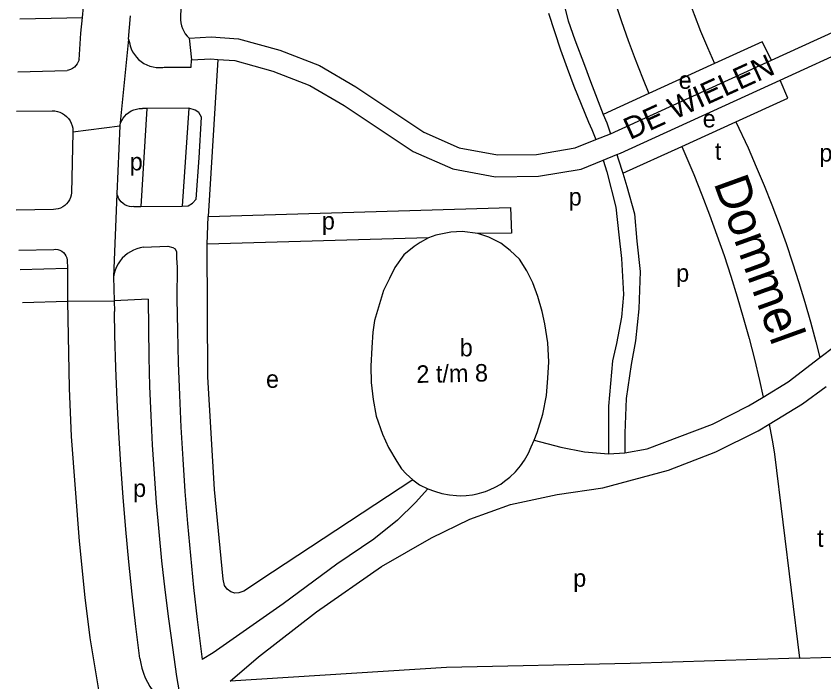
# Model space of a CAD drawing. Extents: x 161494 to 163033, y 383688 to 384862.
# Drawn here: x 161493.5 to 161678.1, y 384018.2 to 384170.2 of the extents above; entities that cross this region are included whole.
import ezdxf

# ---------------------------------------------------------------- set-up
doc = ezdxf.new("R2010")
doc.units = 0
for name, color, linetype in [('BLT_Basislijn', 7, 'Continuous'), ('BLT_Bebouwing', 7, 'Continuous'), ('BLT_Centroide', 7, 'Continuous'), ('BLT_Huisnummer_reeks', 7, 'Continuous'), ('BLT_Straatnaam', 7, 'Continuous'), ('BLT_Vlakafsluiter', 7, 'Continuous'), ('BLT_Waternaam_spoorwegen', 7, 'Continuous')]:
    doc.layers.add(name, color=color, linetype=linetype)

msp = doc.modelspace()

# ---------------------------------------------------------------- linework, layer by layer
at = {"layer": 'BLT_Basislijn'}
for p, q in [((161494.37, 384169.52), (161508.66, 384169.81)), ((161519.21, 384164.89), (161519.66, 384170.2)), ((161493.92, 384157.47), (161505.21, 384157.74)), ((161527.38, 384158.48), (161533.49, 384158.48)), ((161493.59, 384148.45), (161501.73, 384148.56)), ((161523.41, 384149.06), (161522.02, 384126.68)), ((161523.41, 384149.06), (161522.38, 384149.05)), ((161533.01, 384149.16), (161523.41, 384149.06)), ((161533.01, 384149.16), (161531.45, 384126.79)), ((161517.2, 384145.11), (161516.56, 384129.62)), ((161506.51, 384143.59), (161506.15, 384129.84)), ((161625.95, 384141.97), (161629.29, 384143.29)), ((161502.08, 384126.04), (161493.53, 384125.86)), ((161520.45, 384126.66), (161522.02, 384126.68)), ((161522.02, 384126.68), (161531.45, 384126.79)), ((161537.17, 384118.12), (161537.4, 384124.41)), ((161587.76, 384119.54), (161537.17, 384118.12)), ((161494.16, 384116.72), (161502.13, 384116.91)), ((161505.22, 384114.47), (161505.23, 384112.59)), ((161494.47, 384112.27), (161505.23, 384112.59)), ((161505.23, 384112.59), (161505.3, 384105.09)), ((161515.74, 384110.62), (161515.9, 384105.18)), ((161523.73, 384105.57), (161515.9, 384105.18)), ((161515.9, 384105.18), (161515.99, 384102.75)), ((161494.99, 384104.78), (161505.3, 384105.09)), ((161666.8, 384070.18), (161672.52, 384023.56)), ((161672.52, 384023.56), (161687.21, 384024.07))]:
    msp.add_line(p, q, dxfattribs=at)
for points in [[(161540.77, 384239.15), (161539.53, 384233.62), (161538.38, 384228.08), (161537.3, 384222.52), (161536.3, 384216.94), (161535.38, 384211.35), (161534.54, 384205.75), (161533.78, 384200.13), (161533.1, 384194.51), (161532.5, 384188.88), (161531.98, 384183.24), (161531.53, 384177.59), (161531.17, 384171.93), (161531.07, 384170.02)], [(161619.23, 384226.75), (161619.73, 384222.21), (161620.31, 384217.69), (161620.96, 384213.17), (161621.7, 384208.67), (161622.52, 384204.18), (161623.41, 384199.71), (161624.38, 384195.25), (161625.43, 384190.81), (161626.56, 384186.39), (161627.77, 384181.99), (161629.05, 384177.61), (161630.41, 384173.26), (161631.84, 384168.92), (161633.36, 384164.62), (161634.94, 384160.34), (161636.6, 384156.09), (161638.09, 384152.46)], [(161636.29, 384221.31), (161636.75, 384217.31), (161637.3, 384213.32), (161637.92, 384209.34), (161638.62, 384205.37), (161639.4, 384201.42), (161640.26, 384197.48), (161641.2, 384193.56), (161642.22, 384189.66), (161643.31, 384185.78), (161644.48, 384181.93), (161645.72, 384178.09), (161647.05, 384174.29), (161648.44, 384170.51), (161649.91, 384166.76), (161651.46, 384163.03), (161653.09, 384159.31)], [(161508.66, 384169.81), (161508.88, 384172.26), (161509.49, 384178.27), (161510.19, 384184.28), (161510.96, 384190.27), (161511.81, 384196.26), (161512.74, 384202.23), (161513.75, 384208.19), (161514.84, 384214.13), (161515.16, 384215.8)], [(161618.81, 384172.34), (161619.65, 384169.1), (161621.15, 384164.78), (161623.36, 384158.93), (161624.74, 384155.21), (161627.68, 384147.71)], [(161507.89, 384160.21), (161508.34, 384166.24), (161508.66, 384169.81)], [(161531.07, 384170.02), (161531.06, 384169.33), (161531.13, 384168.65), (161531.28, 384167.98), (161531.51, 384167.32), (161531.81, 384166.7), (161532.18, 384166.12), (161532.62, 384165.59), (161533.06, 384165.16)], [(161615.17, 384170.85), (161616.51, 384166.64), (161617.92, 384162.45), (161619.41, 384158.29), (161620.97, 384154.15), (161622.61, 384150.05), (161624.32, 384145.98), (161625.07, 384144.26)], [(161666.14, 384160.13), (161687.96, 384170.1)], [(161519.21, 384164.89), (161519.4, 384164.14), (161519.57, 384163.41), (161519.82, 384162.7), (161520.15, 384162.03), (161520.54, 384161.39), (161521, 384160.8), (161521.52, 384160.27), (161522.1, 384159.79), (161522.72, 384159.37), (161523.39, 384159.03), (161524.08, 384158.75), (161524.8, 384158.55), (161525.54, 384158.44), (161526.29, 384158.4), (161527.04, 384158.44), (161527.38, 384158.48)], [(161533.06, 384165.16), (161538.09, 384165.41), (161544.34, 384164.98), (161553.76, 384162.38), (161562.8, 384158.85), (161571.16, 384154), (161586.64, 384143.64), (161594.77, 384140.08), (161603.48, 384138.46), (161612.42, 384138.57), (161621.22, 384140.08), (161625.95, 384141.97)], [(161666.14, 384160.13), (161663.96, 384164.27), (161653.09, 384159.31)], [(161668.12, 384155.53), (161685.4, 384163.43)], [(161507.89, 384160.21), (161507.73, 384159.73), (161507.5, 384159.27), (161507.2, 384158.86), (161506.84, 384158.49), (161506.43, 384158.19), (161505.98, 384157.96), (161505.49, 384157.8), (161505.21, 384157.74)], [(161533.49, 384158.48), (161533.59, 384160.18)], [(161533.59, 384160.18), (161538.04, 384160.4), (161539.63, 384160.29)], [(161539.63, 384160.29), (161537.4, 384124.41)], [(161539.63, 384160.29), (161543.5, 384160.03), (161552.18, 384157.63), (161560.63, 384154.33), (161568.51, 384149.75), (161584.23, 384139.24), (161593.29, 384135.27), (161603.05, 384133.46), (161612.88, 384133.58), (161622.59, 384135.24), (161627.64, 384137.26)], [(161629.29, 384143.29), (161666.14, 384160.13)], [(161653.09, 384159.31), (161638.09, 384152.46)], [(161630.79, 384138.53), (161631.6, 384138.85), (161668.12, 384155.53)], [(161657.98, 384146.03), (161669.83, 384151.43), (161668.12, 384155.53)], [(161638.09, 384152.46), (161627.68, 384147.71)], [(161501.73, 384148.56), (161502.34, 384148.53), (161502.95, 384148.42), (161503.53, 384148.23), (161504.09, 384147.96), (161504.61, 384147.62), (161505.07, 384147.23), (161505.49, 384146.77), (161505.84, 384146.27), (161506.12, 384145.72), (161506.33, 384145.14), (161506.46, 384144.54), (161506.51, 384143.93), (161506.51, 384143.59)], [(161517.2, 384145.11), (161517.39, 384145.72), (161517.64, 384146.3), (161517.95, 384146.85), (161518.34, 384147.35), (161518.78, 384147.8), (161519.28, 384148.18), (161519.82, 384148.51), (161520.4, 384148.76), (161521, 384148.94), (161521.62, 384149.03), (161522.25, 384149.05), (161522.38, 384149.05)], [(161535.31, 384137.77), (161535.9, 384147.11), (161535.26, 384148.15), (161534.43, 384148.69), (161533.01, 384149.16)], [(161627.68, 384147.71), (161628.49, 384145.8)], [(161628.49, 384145.8), (161629.29, 384143.29)], [(161645.6, 384140.4), (161657.98, 384146.03)], [(161657.98, 384146.03), (161660.74, 384140.08), (161662.63, 384135.78), (161664.44, 384131.45), (161666.18, 384127.08), (161667.84, 384122.69), (161669.43, 384118.27), (161670.94, 384113.83), (161672.38, 384109.36), (161673.74, 384104.86), (161675.02, 384100.35), (161676.22, 384095.81), (161677.12, 384092.19)], [(161625.07, 384144.26), (161625.95, 384141.97)], [(161632.13, 384134.27), (161645.6, 384140.4)], [(161645.6, 384140.4), (161648.35, 384133.97), (161650.19, 384129.39), (161651.96, 384124.78), (161653.65, 384120.14), (161655.27, 384115.48), (161656.82, 384110.79), (161658.28, 384106.07), (161659.67, 384101.34), (161660.99, 384096.58), (161662.22, 384091.8), (161663.38, 384087), (161664.23, 384083.18)], [(161627.64, 384137.26), (161630.79, 384138.53)], [(161630.79, 384138.53), (161631.1, 384137.56), (161632.13, 384134.27)], [(161531.45, 384126.79), (161532.8, 384126.82), (161533.79, 384127.42), (161534.67, 384128.35), (161535.31, 384137.77)], [(161627.64, 384137.26), (161628.51, 384134.64), (161630.57, 384126.57), (161631.2, 384120.24), (161631.84, 384114.85), (161632.31, 384106.62), (161631.84, 384101.39), (161630.73, 384095.38), (161629.78, 384091.42), (161628.83, 384081.13), (161628.83, 384076.53), (161628.83, 384070.24)], [(161632.13, 384134.27), (161633.07, 384131.26), (161634.84, 384124.99), (161635.32, 384118.81), (161636.11, 384111.84), (161635.79, 384103.29), (161635, 384096.01), (161634.05, 384090.63), (161632.94, 384082.87), (161632.63, 384074.95), (161632.63, 384070.47)], [(161506.15, 384129.84), (161506.08, 384129.27), (161505.93, 384128.73), (161505.71, 384128.21), (161505.41, 384127.72), (161505.05, 384127.29), (161504.63, 384126.9), (161504.17, 384126.58), (161503.66, 384126.33), (161503.12, 384126.16), (161502.56, 384126.06), (161502.08, 384126.04)], [(161520.45, 384126.66), (161519.92, 384126.65), (161519.39, 384126.72), (161518.88, 384126.87), (161518.39, 384127.09), (161517.95, 384127.39), (161517.55, 384127.74), (161517.22, 384128.15), (161516.94, 384128.61), (161516.74, 384129.1), (161516.56, 384129.62)], [(161537.4, 384124.41), (161606.46, 384126.5), (161606.72, 384120.63), (161599.02, 384120.5)], [(161677.12, 384092.19), (161680.55, 384094.83), (161688.44, 384103.81), (161694.33, 384114.22), (161697.95, 384122.55)], [(161584.14, 384064.3), (161552.12, 384043.21), (161545.57, 384038.89), (161544.42, 384038.45), (161543.49, 384038.4), (161542.61, 384038.71), (161541.73, 384039.33), (161541.16, 384040.16), (161540.83, 384041.57), (161538.87, 384062.07), (161537.32, 384087.82), (161537.17, 384118.12)], [(161502.13, 384116.91), (161502.61, 384116.92), (161503.08, 384116.84), (161503.53, 384116.7), (161503.95, 384116.47), (161504.32, 384116.18), (161504.65, 384115.83), (161504.91, 384115.44), (161505.1, 384115), (161505.22, 384114.47)], [(161522.64, 384117.38), (161521.85, 384117.24), (161521.09, 384117.02), (161520.35, 384116.73), (161519.64, 384116.36), (161518.97, 384115.93), (161518.35, 384115.43), (161517.78, 384114.87), (161517.28, 384114.26), (161516.83, 384113.6), (161516.46, 384112.9), (161516.15, 384112.16), (161515.92, 384111.4), (161515.74, 384110.62)], [(161522.64, 384117.38), (161528.21, 384117.67), (161529.34, 384117.35), (161529.87, 384117.05), (161530.15, 384116.35), (161530.15, 384114.89), (161530.28, 384112.84), (161530.27, 384105.65)], [(161523.73, 384105.57), (161523.75, 384098.91), (161523.85, 384092.26), (161524.03, 384085.61), (161524.28, 384078.96), (161524.62, 384072.31), (161525.04, 384065.67), (161525.54, 384059.04), (161526.12, 384052.41), (161526.77, 384045.79), (161527.51, 384039.18), (161528.32, 384032.57), (161529.22, 384025.98), (161530.19, 384019.4), (161530.74, 384015.9)], [(161530.27, 384105.65), (161530.38, 384098.31), (161530.56, 384090.97), (161530.83, 384083.63), (161531.17, 384076.3), (161531.59, 384068.97), (161532.1, 384061.64), (161532.68, 384054.32), (161533.34, 384047.01), (161534.08, 384039.7), (161534.9, 384032.41), (161535.81, 384025.12), (161536.05, 384023.25)], [(161505.3, 384105.09), (161505.64, 384085.19), (161506.11, 384074.19), (161507.92, 384050.31), (161509.24, 384037.43)], [(161521.8, 384023.48), (161520.87, 384030.83), (161520.02, 384038.19), (161519.25, 384045.55), (161518.56, 384052.93), (161517.95, 384060.31), (161517.42, 384067.69), (161516.97, 384075.09), (161516.6, 384082.48), (161516.31, 384089.88), (161516.1, 384097.29), (161515.99, 384102.75)], [(161664.23, 384083.18), (161669.89, 384086.63), (161677.12, 384092.19)], [(161665.54, 384076.97), (161673.2, 384081.6), (161678.63, 384085.58)], [(161632.63, 384070.47), (161637.69, 384071.35), (161652.66, 384077), (161660.89, 384081.15), (161664.23, 384083.18)], [(161542.44, 384018.3), (161548.9, 384023.87), (161562.12, 384034.14), (161576.97, 384044.49), (161588.39, 384051.06), (161597.21, 384055.32), (161606.49, 384058.66), (161617.11, 384060.95), (161627.6, 384062.48), (161642.56, 384066.48), (161653.38, 384070.68), (161663.07, 384075.48), (161665.54, 384076.97)], [(161665.54, 384076.97), (161666.38, 384072.49), (161666.8, 384070.18)], [(161611.86, 384073.33), (161617.96, 384071.73), (161623.42, 384070.65), (161628.83, 384070.24)], [(161628.83, 384070.24), (161632.63, 384070.47)], [(161587.59, 384062.26), (161584.76, 384059.09), (161580.63, 384055.05), (161575.22, 384050.7), (161566.78, 384045.02), (161554.56, 384036), (161538.55, 384024.78), (161536.05, 384023.25)], [(161509.24, 384037.43), (161510.4, 384028.21), (161511.89, 384019.04), (161512.89, 384013.17)], [(161521.8, 384023.48), (161521.99, 384022.36), (161522.27, 384021.25), (161522.62, 384020.16), (161523.04, 384019.1), (161523.54, 384018.08), (161524.11, 384017.09), (161524.75, 384016.14), (161525.47, 384015.22)], [(161672.52, 384023.56), (161633.83, 384022.36), (161591.87, 384021.47), (161542.44, 384018.3)]]:
    msp.add_lwpolyline(points, dxfattribs=at)
at = {"layer": 'BLT_Bebouwing'}
for points in [[(161599.02, 384120.5), (161595.4, 384121), (161592.86, 384120.82), (161589.39, 384120.12), (161587.76, 384119.54)], [(161611.86, 384073.33), (161612.55, 384075.07), (161613.83, 384079.24), (161614.69, 384083.52), (161615.04, 384087.46), (161615.21, 384091.25), (161615.04, 384095.53), (161614.35, 384099.88), (161613.71, 384102.71), (161612.73, 384106.13), (161611.57, 384109.25), (161610.21, 384112.01), (161608.5, 384114.7), (161606.42, 384116.66), (161604.28, 384118.29), (161601.53, 384119.68), (161599.02, 384120.5)], [(161587.76, 384119.54), (161585.81, 384118.5), (161584.43, 384117.53), (161582.12, 384115.68), (161580.04, 384112.79), (161578.81, 384110.27), (161577.46, 384107.52), (161576.32, 384103.72), (161575.43, 384100.66), (161575, 384097.97), (161574.77, 384094.49), (161574.54, 384090.27), (161574.66, 384086.53), (161575.13, 384082.65), (161575.82, 384078.83), (161577.2, 384074.72), (161578.59, 384071.66), (161580.5, 384068.44), (161581.6, 384066.76), (161582.61, 384065.62), (161584.14, 384064.3)], [(161610.55, 384070.34), (161611.22, 384071.83), (161611.86, 384073.33)], [(161587.59, 384062.26), (161589.1, 384061.68), (161590.77, 384061.17), (161592.53, 384060.82), (161594.12, 384060.68), (161594.98, 384060.66), (161596.38, 384060.71), (161597.76, 384060.88), (161598.85, 384061.12), (161599.94, 384061.4), (161600.75, 384061.64), (161601.8, 384062.06), (161602.94, 384062.62), (161604.23, 384063.32), (161605.14, 384063.97), (161606.33, 384064.87), (161607.58, 384066.09), (161608.74, 384067.45), (161609.68, 384068.77), (161610.55, 384070.34)], [(161584.14, 384064.3), (161585.69, 384063.17), (161587.59, 384062.26)]]:
    msp.add_lwpolyline(points, dxfattribs=at)
at = {"layer": 'BLT_Vlakafsluiter'}
for p, q in [((161519.21, 384164.89), (161517.2, 384145.11)), ((161533.06, 384165.16), (161533.59, 384160.18)), ((161506.51, 384143.76), (161517.2, 384145.11)), ((161516.56, 384129.62), (161515.74, 384110.62)), ((161505.3, 384105.09), (161515.9, 384105.18))]:
    msp.add_line(p, q, dxfattribs=at)

# ---------------------------------------------------------------- texts
at = {"layer": 'BLT_Centroide'}
for s, p in [('e', (161644.9, 384153.57)), ('e', (161650.39, 384144.75)), ('t', (161653.16, 384137.36)), ('p', (161677.04, 384136.94)), ('p', (161519.48, 384134.94)), ('p', (161619.77, 384126.91)), ('p', (161563.38, 384121.42)), ('p', (161644.33, 384109.51)), ('b', (161594.88, 384092.48)), ('e', (161550.61, 384085.3)), ('p', (161520.26, 384060.37)), ('t', (161676.52, 384048.99)), ('p', (161620.81, 384039.87))]:
    msp.add_text(s, height=4, dxfattribs=at).set_placement(p)
at = {"layer": 'BLT_Huisnummer_reeks'}
msp.add_text('2 t/m 8', height=4, rotation=1.2193, dxfattribs=at).set_placement((161585.02, 384086.4))
at = {"layer": 'BLT_Straatnaam'}
msp.add_text('DE WIELEN', height=5, rotation=24.5068, dxfattribs=at).set_placement((161633.78, 384141.84))
at = {"layer": 'BLT_Waternaam_spoorwegen'}
msp.add_text('Dommel', height=8, rotation=289.8587, dxfattribs=at).set_placement((161652.83, 384132.08))

doc.saveas('drawing.dxf')
